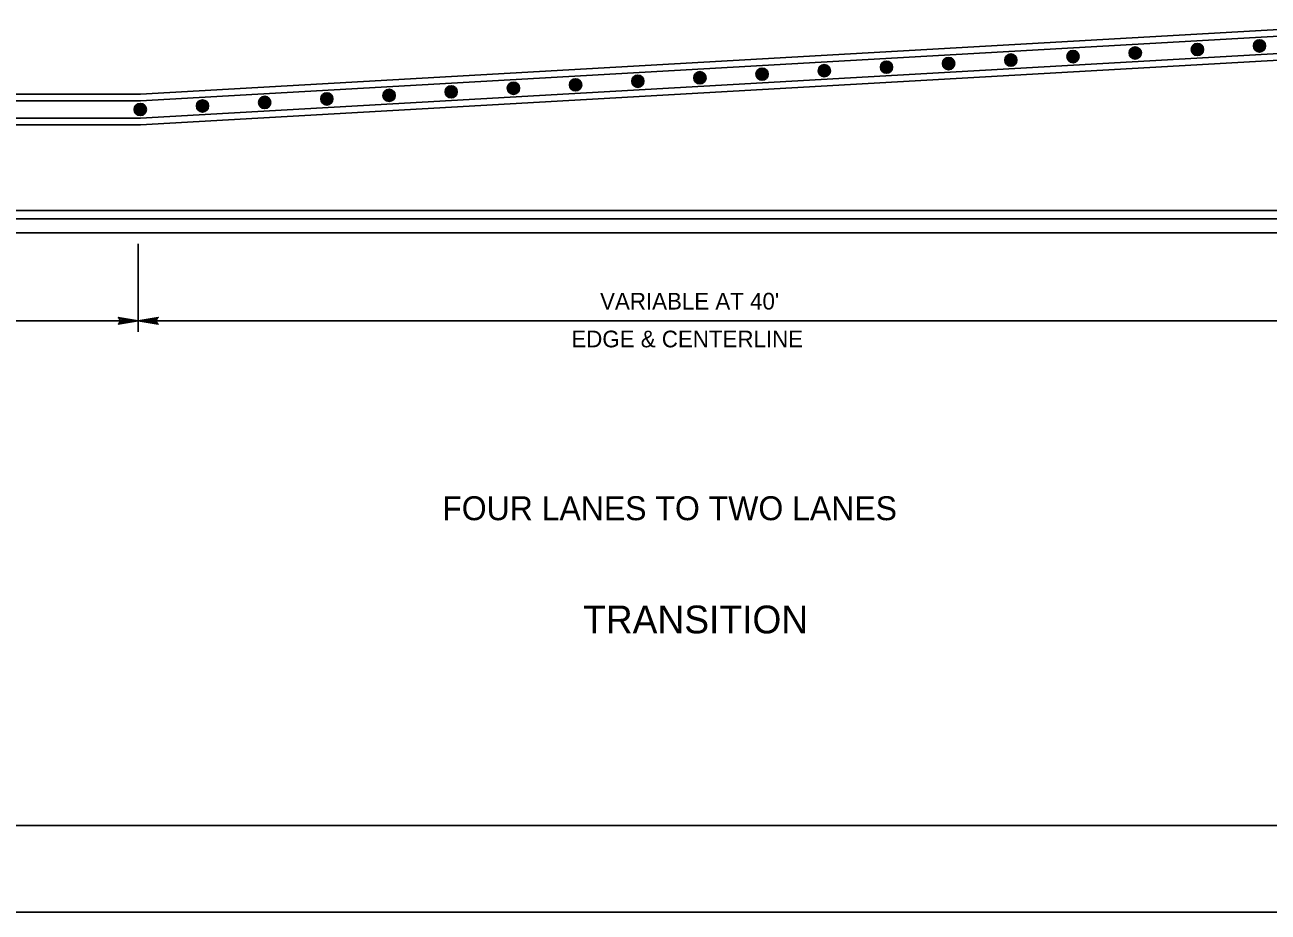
# Model space of a CAD drawing. Extents: x 639362 to 641108, y 298458 to 299646.
# Drawn here: x 639565.1 to 639788.7, y 298457.6 to 298617.3 of the extents above; entities that cross this region are included whole.
import ezdxf

# ---------------------------------------------------------------- set-up
doc = ezdxf.new("R2010")
doc.units = 0
for name, color, linetype in [('1', 7, 'Continuous'), ('2', 7, 'Continuous'), ('3', 7, 'Continuous'), ('PLT-BNDY', 7, 'Continuous')]:
    doc.layers.add(name, color=color, linetype=linetype)

# ---------------------------------------------------------------- blocks, each defined once
blk = doc.blocks.new('RARROW')
at = {"layer": '3'}
blk.add_lwpolyline([(-2.2695, 0.285), (-2.184875, 0.12075), (0, 0), (-2.2695, 0.285), (-2.38575, 0.384625), (0, 0), (-2.183125, -0.108), (-2.262875, -0.2705), (0, 0), (-2.38575, -0.379125), (-2.262875, -0.2705)], dxfattribs=at)

msp = doc.modelspace()

# ---------------------------------------------------------------- linework, layer by layer
at = {"layer": '1'}
for p, q in [((640189.27, 298473.19), (639403.27, 298473.19)), ((639403.27, 298473.19), (639989.27, 298473.19))]:
    msp.add_line(p, q, dxfattribs=at)
at = {"layer": '2'}
for p, q in [((639797.98, 298616.83), (639585.9, 298604.78)), ((639585.93, 298603.58), (639798.02, 298615.63)), ((639797.98, 298612.52), (639585.9, 298600.47)), ((639585.93, 298599.27), (639798.02, 298611.32)), ((639585.9, 298604.78), (639431.63, 298604.78)), ((639431.63, 298603.58), (639585.93, 298603.58)), ((639585.9, 298600.47), (639431.63, 298600.47)), ((639431.63, 298599.27), (639585.93, 298599.27)), ((639431.63, 298583.85), (639951.12, 298583.85)), ((639431.63, 298582.35), (639951.12, 298582.35)), ((639431.63, 298579.85), (639951.12, 298579.85)), ((639585.52, 298577.85), (639585.52, 298562.02)), ((639585.52, 298564.02), (639451.32, 298564.02)), ((639798, 298564.02), (639585.52, 298564.02))]:
    msp.add_line(p, q, dxfattribs=at)
for centre, radius in [((639753.65, 298611.55), 1.1), ((639753.65, 298611.55), 1.02), ((639753.65, 298611.55), 0.946), ((639764.84, 298612.19), 1.1), ((639764.84, 298612.19), 1.02), ((639764.84, 298612.19), 0.946), ((639764.84, 298612.19), 0.868), ((639764.84, 298612.19), 0.789), ((639764.84, 298612.19), 0.711), ((639764.84, 298612.19), 0.633), ((639764.84, 298612.19), 0.554), ((639764.84, 298612.19), 0.476), ((639764.84, 298612.19), 0.398), ((639764.84, 298612.19), 0.32), ((639776.02, 298612.82), 1.1), ((639776.02, 298612.82), 1.02), ((639776.02, 298612.82), 0.946), ((639776.02, 298612.82), 0.868), ((639776.02, 298612.82), 0.789), ((639776.02, 298612.82), 0.711), ((639776.02, 298612.82), 0.633), ((639776.02, 298612.82), 0.554), ((639776.02, 298612.82), 0.476), ((639776.02, 298612.82), 0.398), ((639776.02, 298612.82), 0.32), ((639776.02, 298612.82), 0.241), ((639776.02, 298612.82), 0.163), ((639776.02, 298612.82), 0.0846), ((639787.2, 298613.46), 1.1), ((639787.2, 298613.46), 1.02), ((639787.2, 298613.46), 0.946), ((639787.2, 298613.46), 0.868), ((639787.2, 298613.46), 0.789), ((639787.2, 298613.46), 0.711), ((639787.2, 298613.46), 0.633), ((639787.2, 298613.46), 0.554), ((639787.2, 298613.46), 0.476), ((639787.2, 298613.46), 0.398), ((639787.2, 298613.46), 0.32), ((639787.2, 298613.46), 0.241), ((639787.2, 298613.46), 0.163), ((639787.2, 298613.46), 0.0846), ((639720.1, 298609.65), 1.1), ((639720.1, 298609.65), 1.02), ((639720.1, 298609.65), 0.946), ((639720.1, 298609.65), 0.868), ((639720.1, 298609.65), 0.789), ((639720.1, 298609.65), 0.711), ((639720.1, 298609.65), 0.633), ((639731.28, 298610.28), 1.1), ((639731.28, 298610.28), 1.02), ((639731.28, 298610.28), 0.946), ((639731.28, 298610.28), 0.868), ((639731.28, 298610.28), 0.789), ((639731.28, 298610.28), 0.711), ((639731.28, 298610.28), 0.633), ((639731.28, 298610.28), 0.554), ((639731.28, 298610.28), 0.476), ((639731.28, 298610.28), 0.398), ((639731.28, 298610.28), 0.32), ((639731.28, 298610.28), 0.241), ((639731.28, 298610.28), 0.163), ((639731.28, 298610.28), 0.0846), ((639742.47, 298610.92), 1.1), ((639742.47, 298610.92), 1.02), ((639742.47, 298610.92), 0.946), ((639742.47, 298610.92), 0.868), ((639742.47, 298610.92), 0.789), ((639742.47, 298610.92), 0.711), ((639742.47, 298610.92), 0.633), ((639742.47, 298610.92), 0.554), ((639742.47, 298610.92), 0.476), ((639742.47, 298610.92), 0.398), ((639742.47, 298610.92), 0.32), ((639742.47, 298610.92), 0.241), ((639742.47, 298610.92), 0.163), ((639742.47, 298610.92), 0.0846), ((639753.65, 298611.55), 0.868), ((639753.65, 298611.55), 0.789), ((639753.65, 298611.55), 0.711), ((639753.65, 298611.55), 0.633), ((639753.65, 298611.55), 0.554), ((639753.65, 298611.55), 0.476), ((639753.65, 298611.55), 0.398), ((639753.65, 298611.55), 0.32), ((639753.65, 298611.55), 0.241), ((639753.65, 298611.55), 0.163), ((639753.65, 298611.55), 0.0846), ((639764.84, 298612.19), 0.241), ((639764.84, 298612.19), 0.163), ((639764.84, 298612.19), 0.0846), ((639675.37, 298607.11), 1.1), ((639675.37, 298607.11), 1.02), ((639675.37, 298607.11), 0.946), ((639686.55, 298607.74), 1.1), ((639686.55, 298607.74), 1.02), ((639686.55, 298607.74), 0.946), ((639686.55, 298607.74), 0.868), ((639686.55, 298607.74), 0.789), ((639686.55, 298607.74), 0.711), ((639686.55, 298607.74), 0.633), ((639686.55, 298607.74), 0.554), ((639686.55, 298607.74), 0.476), ((639686.55, 298607.74), 0.398), ((639686.55, 298607.74), 0.32), ((639697.73, 298608.38), 1.1), ((639697.73, 298608.38), 1.02), ((639697.73, 298608.38), 0.946), ((639697.73, 298608.38), 0.868), ((639697.73, 298608.38), 0.789), ((639697.73, 298608.38), 0.711), ((639697.73, 298608.38), 0.633), ((639697.73, 298608.38), 0.554), ((639697.73, 298608.38), 0.476), ((639697.73, 298608.38), 0.398), ((639697.73, 298608.38), 0.32), ((639697.73, 298608.38), 0.241), ((639697.73, 298608.38), 0.163), ((639697.73, 298608.38), 0.0846), ((639708.92, 298609.01), 1.1), ((639708.92, 298609.01), 1.02), ((639708.92, 298609.01), 0.946), ((639708.92, 298609.01), 0.868), ((639708.92, 298609.01), 0.789), ((639708.92, 298609.01), 0.711), ((639708.92, 298609.01), 0.633), ((639708.92, 298609.01), 0.554), ((639708.92, 298609.01), 0.476), ((639708.92, 298609.01), 0.398), ((639708.92, 298609.01), 0.32), ((639708.92, 298609.01), 0.241), ((639708.92, 298609.01), 0.163), ((639708.92, 298609.01), 0.0846), ((639720.1, 298609.65), 0.554), ((639720.1, 298609.65), 0.476), ((639720.1, 298609.65), 0.398), ((639720.1, 298609.65), 0.32), ((639720.1, 298609.65), 0.241), ((639720.1, 298609.65), 0.163), ((639720.1, 298609.65), 0.0846), ((639641.81, 298605.2), 1.1), ((639641.81, 298605.2), 1.02), ((639641.81, 298605.2), 0.946), ((639641.81, 298605.2), 0.868), ((639641.81, 298605.2), 0.789), ((639641.81, 298605.2), 0.711), ((639641.81, 298605.2), 0.633), ((639641.81, 298605.2), 0.554), ((639653, 298605.84), 1.1), ((639653, 298605.84), 1.02), ((639653, 298605.84), 0.946), ((639653, 298605.84), 0.868), ((639653, 298605.84), 0.789), ((639653, 298605.84), 0.711), ((639653, 298605.84), 0.633), ((639653, 298605.84), 0.554), ((639653, 298605.84), 0.476), ((639653, 298605.84), 0.398), ((639653, 298605.84), 0.32), ((639653, 298605.84), 0.241), ((639653, 298605.84), 0.163), ((639653, 298605.84), 0.0846), ((639664.18, 298606.47), 1.1), ((639664.18, 298606.47), 1.02), ((639664.18, 298606.47), 0.946), ((639664.18, 298606.47), 0.868), ((639664.18, 298606.47), 0.789), ((639664.18, 298606.47), 0.711), ((639664.18, 298606.47), 0.633), ((639664.18, 298606.47), 0.554), ((639664.18, 298606.47), 0.476), ((639664.18, 298606.47), 0.398), ((639664.18, 298606.47), 0.32), ((639664.18, 298606.47), 0.241), ((639664.18, 298606.47), 0.163), ((639664.18, 298606.47), 0.0846), ((639675.37, 298607.11), 0.868), ((639675.37, 298607.11), 0.789), ((639675.37, 298607.11), 0.711), ((639675.37, 298607.11), 0.633), ((639675.37, 298607.11), 0.554), ((639675.37, 298607.11), 0.476), ((639675.37, 298607.11), 0.398), ((639675.37, 298607.11), 0.32), ((639675.37, 298607.11), 0.241), ((639675.37, 298607.11), 0.163), ((639675.37, 298607.11), 0.0846), ((639686.55, 298607.74), 0.241), ((639686.55, 298607.74), 0.163), ((639686.55, 298607.74), 0.0846), ((639597.08, 298602.66), 1.1), ((639597.08, 298602.66), 1.02), ((639597.08, 298602.66), 0.946), ((639597.08, 298602.66), 0.868), ((639608.26, 298603.3), 1.1), ((639608.26, 298603.3), 1.02), ((639608.26, 298603.3), 0.946), ((639608.26, 298603.3), 0.868), ((639608.26, 298603.3), 0.789), ((639608.26, 298603.3), 0.711), ((639608.26, 298603.3), 0.633), ((639608.26, 298603.3), 0.554), ((639608.26, 298603.3), 0.476), ((639608.26, 298603.3), 0.398), ((639608.26, 298603.3), 0.32), ((639608.26, 298603.3), 0.241), ((639619.45, 298603.93), 1.1), ((639619.45, 298603.93), 1.02), ((639619.45, 298603.93), 0.946), ((639619.45, 298603.93), 0.868), ((639619.45, 298603.93), 0.789), ((639619.45, 298603.93), 0.711), ((639619.45, 298603.93), 0.633), ((639619.45, 298603.93), 0.554), ((639619.45, 298603.93), 0.476), ((639619.45, 298603.93), 0.398), ((639619.45, 298603.93), 0.32), ((639619.45, 298603.93), 0.241), ((639619.45, 298603.93), 0.163), ((639619.45, 298603.93), 0.0846), ((639630.63, 298604.57), 1.1), ((639630.63, 298604.57), 1.02), ((639630.63, 298604.57), 0.946), ((639630.63, 298604.57), 0.868), ((639630.63, 298604.57), 0.789), ((639630.63, 298604.57), 0.711), ((639630.63, 298604.57), 0.633), ((639630.63, 298604.57), 0.554), ((639630.63, 298604.57), 0.476), ((639630.63, 298604.57), 0.398), ((639630.63, 298604.57), 0.32), ((639630.63, 298604.57), 0.241), ((639630.63, 298604.57), 0.163), ((639630.63, 298604.57), 0.0846), ((639641.81, 298605.2), 0.476), ((639641.81, 298605.2), 0.398), ((639641.81, 298605.2), 0.32), ((639641.81, 298605.2), 0.241), ((639641.81, 298605.2), 0.163), ((639641.81, 298605.2), 0.0846), ((639585.89, 298602.03), 1.1), ((639585.89, 298602.03), 1.02), ((639585.89, 298602.03), 0.946), ((639585.89, 298602.03), 0.868), ((639585.89, 298602.03), 0.789), ((639585.89, 298602.03), 0.711), ((639585.89, 298602.03), 0.633), ((639585.89, 298602.03), 0.554), ((639585.89, 298602.03), 0.476), ((639585.89, 298602.03), 0.398), ((639585.89, 298602.03), 0.32), ((639585.89, 298602.03), 0.241), ((639585.89, 298602.03), 0.163), ((639585.89, 298602.03), 0.0846), ((639597.08, 298602.66), 0.789), ((639597.08, 298602.66), 0.711), ((639597.08, 298602.66), 0.633), ((639597.08, 298602.66), 0.554), ((639597.08, 298602.66), 0.476), ((639597.08, 298602.66), 0.398), ((639597.08, 298602.66), 0.32), ((639597.08, 298602.66), 0.241), ((639597.08, 298602.66), 0.163), ((639597.08, 298602.66), 0.0846), ((639608.26, 298603.3), 0.163), ((639608.26, 298603.3), 0.0846)]:
    msp.add_circle(centre, radius, dxfattribs=at)
at = {"layer": 'PLT-BNDY'}
msp.add_lwpolyline([(639362.31, 299051.63), (640203.31, 299051.63), (640203.31, 298457.63), (639362.31, 298457.63)], close=True, dxfattribs=at)

# ---------------------------------------------------------------- block references
at = {"layer": '2', "xscale": 1.5089217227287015, "yscale": 1.5711553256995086}
msp.add_blockref('RARROW', (639585.52, 298564.02), dxfattribs=at)
at = {"layer": '2', "xscale": 1.5089217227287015, "yscale": 1.5711553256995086, "rotation": 180}
msp.add_blockref('RARROW', (639585.52, 298564.02), dxfattribs=at)

# ---------------------------------------------------------------- texts
at = {"layer": '2'}
for s, height, p in [("VARIABLE AT 40'", 3, (639668.59, 298566.04)), ('EDGE & CENTERLINE', 3, (639663.42, 298559.24)), ('FOUR LANES TO TWO LANES', 4.3, (639640.2, 298528.14)), ('TRANSITION', 5, (639665.53, 298507.78))]:
    msp.add_text(s, height=height, dxfattribs=at).set_placement(p)

doc.saveas('drawing.dxf')
